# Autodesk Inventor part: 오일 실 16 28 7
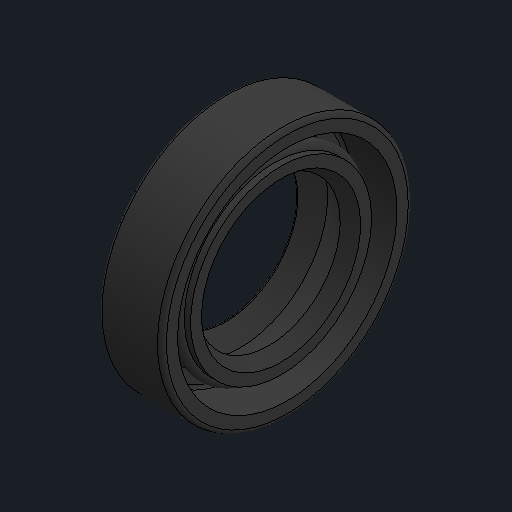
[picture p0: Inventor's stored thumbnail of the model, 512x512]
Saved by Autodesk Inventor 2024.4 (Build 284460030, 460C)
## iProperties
Created: 2026-09
Part Number: 오일 실 16 28 7
Material: 고무
Description: 오일-실
Document SubType Name: Modeling
Designer: user
Density: 0.93 g/cm^3
Appearance: 기본값
Author: jhkim
Sending System: Autodesk Inventor 2027
Preprocessor: ST-DEVELOPER v20.1
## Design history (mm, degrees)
feature "Solid1"
node "솔리드1"
